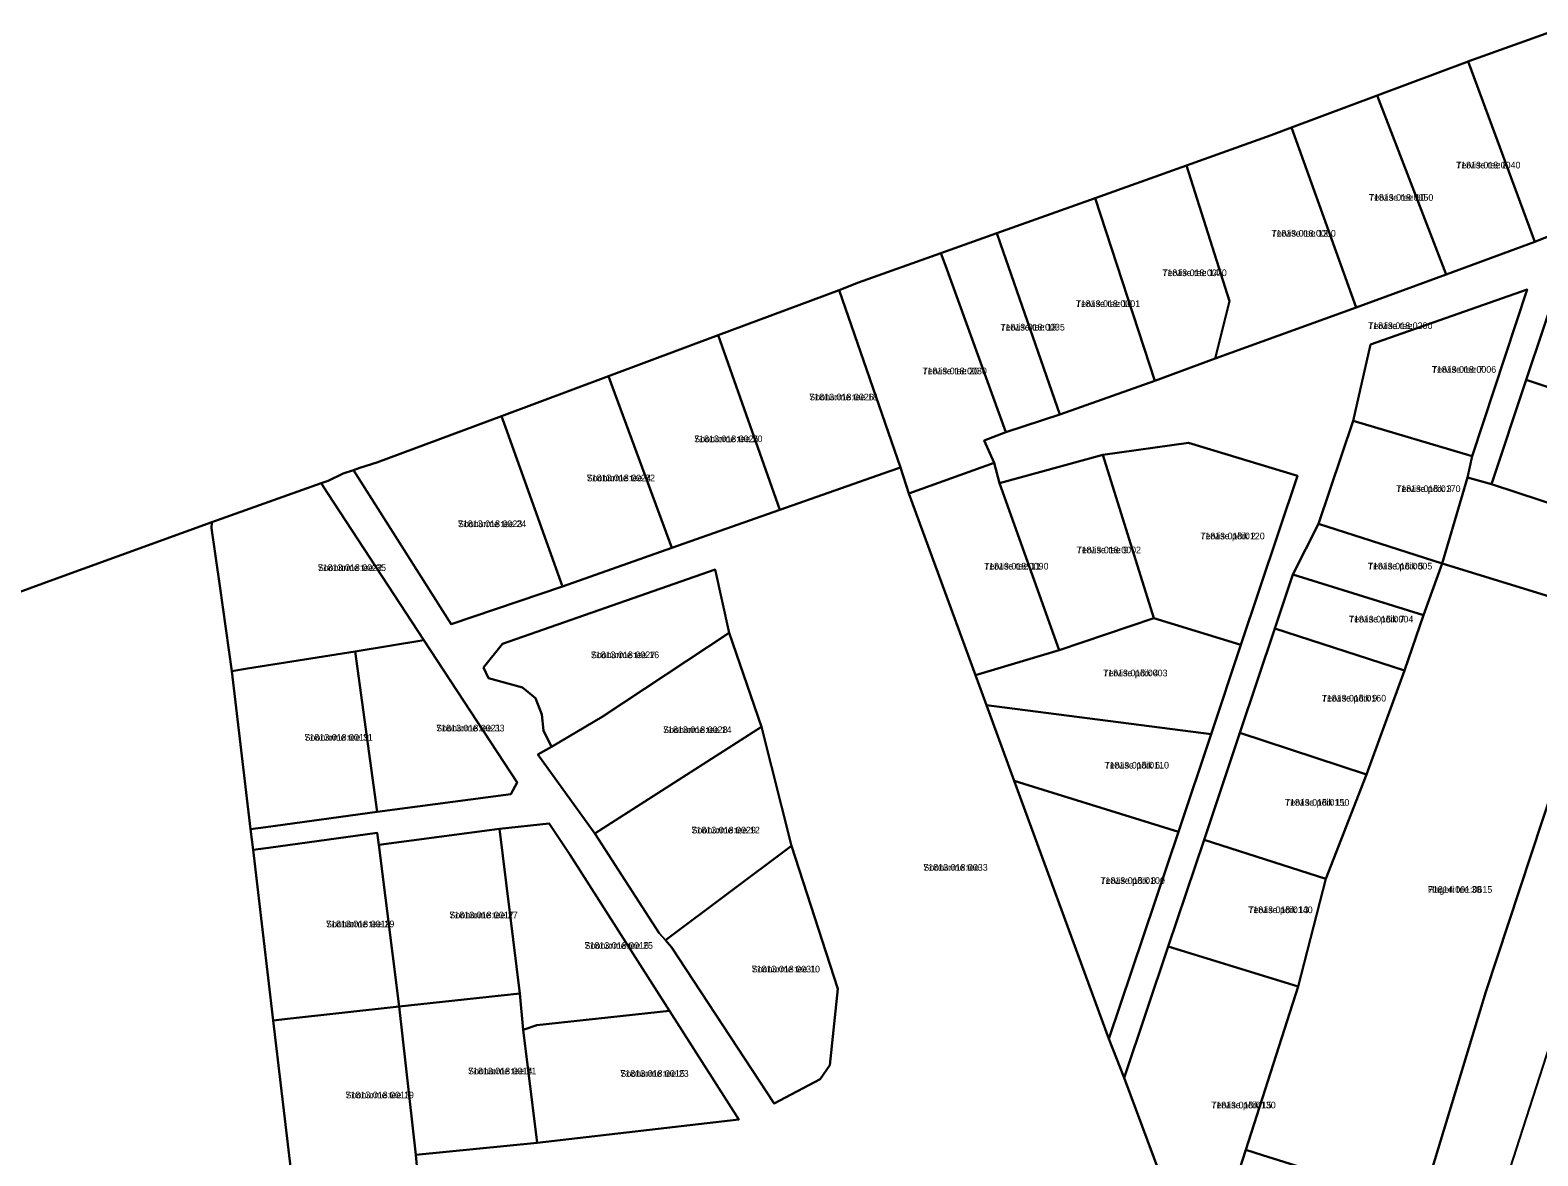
# Model space of a CAD drawing. Extents: x 529768 to 552006, y 6562269 to 6580975.
# Drawn here: x 537994.7 to 538334.3, y 6564944.1 to 6565197.7 of the extents above; entities that cross this region are included whole.
import ezdxf

# ---------------------------------------------------------------- set-up
doc = ezdxf.new("R2010")
doc.units = 0
for name, color, linetype in [('L_AADRESS', 7, 'Continuous'), ('PIIR', 7, 'Continuous'), ('TUNNUS', 7, 'Continuous')]:
    doc.layers.add(name, color=color, linetype=linetype)

msp = doc.modelspace()

# ---------------------------------------------------------------- linework, layer by layer
at = {"layer": 'PIIR'}
for points in [[(538338.26, 6565197.72), (538318.76, 6565190.73), (538318.58, 6565190.66), (538298.12, 6565183), (538278.82, 6565175.77), (538274.18, 6565174.03), (538255.15, 6565167.23), (538234.61, 6565159.87), (538212.42, 6565151.96), (538199.86, 6565147.46), (538181.3, 6565140.83), (538176.91, 6565139.17), (538149.69, 6565128.98), (538124.96, 6565119.74), (538100.9, 6565110.76), (538072.84, 6565100.28), (538068.99, 6565099.13), (538067.53, 6565098.62), (538065.21, 6565097.82), (538061.86, 6565096.19), (538060.26, 6565095.62), (538035.66, 6565086.9), (537999.88, 6565073.9), (537935.47, 6565050.3)], [(538339.3, 6565141.77), (538331.67, 6565118.94), (538323.82, 6565095.46), (538318.43, 6565096.95), (538319.45, 6565101.76), (538331.84, 6565139.3), (538296.57, 6565126.87), (538292.67, 6565109.72), (538284.89, 6565086.51), (538279.13, 6565075.05), (538275.06, 6565062.91), (538267.18, 6565039.43), (538259.11, 6565015.32), (538251.03, 6564991.25), (538241.13, 6564961.69), (538237.68, 6564970.44), (538253.34, 6565017.1), (538260.67, 6565039.07), (538267.42, 6565059.23), (538280.17, 6565097.32), (538255.63, 6565104.77), (538236.34, 6565102.01), (538213.04, 6565095.67), (538211.84, 6565100.22), (538209.58, 6565105.3), (538214.47, 6565107.11), (538226.65, 6565111.14), (538248.01, 6565118.69), (538261.59, 6565123.77), (538293.38, 6565135.23), (538313.64, 6565142.65), (538333.61, 6565150.05), (538353.15, 6565157.92)], [(538082.07, 6564939.35), (538081.58, 6564944.34), (538108.89, 6564947.05), (538154.33, 6564952.3), (538138.74, 6564976.77), (538116.27, 6565012.03), (538111.6, 6565019.01), (538100.44, 6565017.78), (538073.26, 6565014.19), (538072.89, 6565016.87), (538048.39, 6565013.51), (538044.93, 6565013.03), (538044.38, 6565017.68), (538047.81, 6565018.16), (538072.86, 6565021.59), (538102.97, 6565025.57), (538104.44, 6565028.24), (538083.43, 6565060.28), (538061.77, 6565093.31), (538060.26, 6565095.62), (538061.86, 6565096.19), (538065.21, 6565097.82), (538067.53, 6565098.62), (538069.12, 6565096.12), (538089.53, 6565063.89), (538114.61, 6565072.34), (538139.25, 6565081.05), (538163.58, 6565089.64), (538188.32, 6565098.37), (538190.71, 6565099.21), (538192.64, 6565093.3), (538207.61, 6565052.42), (538210.09, 6565045.62), (538216.32, 6565028.6), (538237.68, 6564970.44), (538241.13, 6564961.69), (538250.41, 6564936.65)], [(537935.47, 6565050.3), (537999.88, 6565073.9), (538035.66, 6565086.9), (538035.56, 6565085.5), (538037.44, 6565072.54), (538040.16, 6565053.32), (538044.38, 6565017.68), (538044.93, 6565013.03), (538049.48, 6564974.58), (538053.98, 6564936.59), (538054.5, 6564932.17), (538059.83, 6564887.16), (538062.92, 6564887.96), (538065.7, 6564865.25), (538069.71, 6564832.47), (538070.84, 6564823.25), (538069.52, 6564811.11), (538075.4, 6564804.88), (538059.69, 6564796.82), (538028.15, 6564780.63), (537982.75, 6564773.59)], [(538308.01, 6564933.07), (538322.57, 6564981.02), (538350.55, 6565065.93)], [(538336.86, 6564968.94), (538321.95, 6564922.64)]]:
    msp.add_lwpolyline(points, dxfattribs=at)
for points in [[(538318.58, 6565190.66), (538318.76, 6565190.73), (538338.26, 6565197.72), (538353.15, 6565157.92), (538333.61, 6565150.05)], [(538298.12, 6565183), (538318.58, 6565190.66), (538333.61, 6565150.05), (538313.64, 6565142.65)], [(538278.82, 6565175.77), (538298.12, 6565183), (538313.64, 6565142.65), (538293.38, 6565135.23)], [(538261.59, 6565123.77), (538264.81, 6565136.63), (538255.15, 6565167.23), (538274.18, 6565174.03), (538278.82, 6565175.77), (538293.38, 6565135.23)], [(538234.61, 6565159.87), (538255.15, 6565167.23), (538264.81, 6565136.63), (538261.59, 6565123.77), (538248.01, 6565118.69)], [(538248.01, 6565118.69), (538226.65, 6565111.14), (538213.27, 6565149.6), (538212.42, 6565151.96), (538234.61, 6565159.87)], [(538213.27, 6565149.6), (538226.65, 6565111.14), (538214.47, 6565107.11), (538200.84, 6565144.73), (538199.86, 6565147.46), (538212.42, 6565151.96)], [(538192.64, 6565093.3), (538190.71, 6565099.21), (538176.91, 6565139.17), (538181.3, 6565140.83), (538199.86, 6565147.46), (538200.84, 6565144.73), (538214.47, 6565107.11), (538209.58, 6565105.3), (538211.84, 6565100.22)], [(538339.3, 6565141.77), (538372.43, 6565133.83), (538364.67, 6565108), (538331.67, 6565118.94)], [(538149.69, 6565128.98), (538176.91, 6565139.17), (538190.71, 6565099.21), (538188.32, 6565098.37), (538163.58, 6565089.64), (538150.58, 6565126.48)], [(538319.45, 6565101.76), (538292.67, 6565109.72), (538296.57, 6565126.87), (538331.84, 6565139.3)], [(538124.96, 6565119.74), (538149.69, 6565128.98), (538150.58, 6565126.48), (538163.58, 6565089.64), (538139.25, 6565081.05), (538125.87, 6565117.29)], [(538100.9, 6565110.76), (538124.96, 6565119.74), (538125.87, 6565117.29), (538139.25, 6565081.05), (538114.61, 6565072.34), (538101.78, 6565108.3)], [(538356.96, 6565084.57), (538323.82, 6565095.46), (538331.67, 6565118.94), (538364.67, 6565108)], [(538067.53, 6565098.62), (538068.99, 6565099.13), (538072.84, 6565100.28), (538100.9, 6565110.76), (538101.78, 6565108.3), (538114.61, 6565072.34), (538089.53, 6565063.89), (538069.12, 6565096.12)], [(538292.67, 6565109.72), (538319.45, 6565101.76), (538318.43, 6565096.95), (538312.76, 6565077.58), (538284.89, 6565086.51)], [(538236.34, 6565102.01), (538255.63, 6565104.77), (538280.17, 6565097.32), (538267.42, 6565059.23), (538247.76, 6565065.21)], [(538211.84, 6565100.22), (538213.04, 6565095.67), (538226.49, 6565058.01), (538207.61, 6565052.42), (538192.64, 6565093.3)], [(538247.76, 6565065.21), (538226.49, 6565058.01), (538213.04, 6565095.67), (538236.34, 6565102.01)], [(538318.43, 6565096.95), (538323.82, 6565095.46), (538356.96, 6565084.57), (538350.55, 6565065.93), (538312.76, 6565077.58)], [(538035.66, 6565086.9), (538060.26, 6565095.62), (538061.77, 6565093.31), (538083.43, 6565060.28), (538067.92, 6565057.76), (538043.69, 6565053.89), (538040.16, 6565053.32), (538037.44, 6565072.54), (538035.56, 6565085.5)], [(538308.49, 6565065.91), (538279.13, 6565075.05), (538284.89, 6565086.51), (538312.76, 6565077.58)], [(538096.83, 6565054.16), (538101.11, 6565059.46), (538149.01, 6565076.21), (538152.13, 6565061.95), (538123.57, 6565043.01), (538112.13, 6565036.24), (538110.34, 6565039.92), (538109.96, 6565043.52), (538108.53, 6565047.24), (538105.65, 6565049.59), (538097.92, 6565051.69)], [(538096.83, 6565054.16), (538097.92, 6565051.69), (538105.65, 6565049.59), (538108.53, 6565047.24), (538109.96, 6565043.52), (538110.34, 6565039.92), (538112.13, 6565036.24), (538109.06, 6565034.51), (538121.87, 6565016.76), (538136.42, 6564994.24), (538137.79, 6564992.69), (538139.19, 6564991.14), (538162.28, 6564955.91), (538172.65, 6564961.39), (538174.84, 6564964.56), (538176.66, 6564981.73), (538166.17, 6565013.93), (538159.4, 6565040.78), (538152.13, 6565061.95), (538149.01, 6565076.21), (538101.11, 6565059.46)], [(538312.76, 6565077.58), (538350.55, 6565065.93), (538322.57, 6564981.02), (538308.01, 6564933.07), (538272.28, 6564944.25), (538268.48, 6564945.44), (538280.32, 6564982.23), (538286.55, 6565006.52), (538295.71, 6565030), (538304.22, 6565053.48), (538308.49, 6565065.91)], [(538304.22, 6565053.48), (538275.06, 6565062.91), (538279.13, 6565075.05), (538308.49, 6565065.91)], [(538260.67, 6565039.07), (538210.09, 6565045.62), (538207.61, 6565052.42), (538226.49, 6565058.01), (538247.76, 6565065.21), (538267.42, 6565059.23)], [(538275.06, 6565062.91), (538304.22, 6565053.48), (538295.71, 6565030), (538267.18, 6565039.43)], [(538067.92, 6565057.76), (538083.43, 6565060.28), (538104.44, 6565028.24), (538102.97, 6565025.57), (538072.86, 6565021.59)], [(538109.06, 6565034.51), (538112.13, 6565036.24), (538123.57, 6565043.01), (538152.13, 6565061.95), (538159.4, 6565040.78), (538121.87, 6565016.76)], [(538040.16, 6565053.32), (538043.69, 6565053.89), (538067.92, 6565057.76), (538072.86, 6565021.59), (538047.81, 6565018.16), (538044.38, 6565017.68)], [(538210.09, 6565045.62), (538260.67, 6565039.07), (538253.34, 6565017.1), (538216.32, 6565028.6)], [(538121.87, 6565016.76), (538159.4, 6565040.78), (538166.17, 6565013.93), (538137.79, 6564992.69), (538136.42, 6564994.24)], [(538267.18, 6565039.43), (538295.71, 6565030), (538286.55, 6565006.52), (538259.11, 6565015.32)], [(538253.34, 6565017.1), (538237.68, 6564970.44), (538216.32, 6565028.6)], [(538100.44, 6565017.78), (538111.6, 6565019.01), (538116.27, 6565012.03), (538138.74, 6564976.77), (538108.86, 6564973.52), (538105.8, 6564972.47), (538105.05, 6564980.66)], [(538044.93, 6565013.03), (538048.39, 6565013.51), (538072.89, 6565016.87), (538073.26, 6565014.19), (538077.81, 6564977.74), (538052.69, 6564974.94), (538049.48, 6564974.58)], [(538073.26, 6565014.19), (538100.44, 6565017.78), (538105.05, 6564980.66), (538077.81, 6564977.74)], [(538259.11, 6565015.32), (538286.55, 6565006.52), (538280.32, 6564982.23), (538251.03, 6564991.25)], [(538137.79, 6564992.69), (538166.17, 6565013.93), (538176.66, 6564981.73), (538174.84, 6564964.56), (538172.65, 6564961.39), (538162.28, 6564955.91), (538139.19, 6564991.14)], [(538241.13, 6564961.69), (538251.03, 6564991.25), (538280.32, 6564982.23), (538268.48, 6564945.44), (538259.79, 6564918.41), (538258.57, 6564914.59), (538255.85, 6564921.95), (538250.41, 6564936.65)], [(538049.48, 6564974.58), (538052.69, 6564974.94), (538077.81, 6564977.74), (538081.58, 6564944.34), (538082.07, 6564939.35), (538057.23, 6564936.91), (538053.98, 6564936.59)], [(538077.81, 6564977.74), (538105.05, 6564980.66), (538105.8, 6564972.47), (538108.89, 6564947.05), (538081.58, 6564944.34)], [(538105.8, 6564972.47), (538108.86, 6564973.52), (538138.74, 6564976.77), (538154.33, 6564952.3), (538108.89, 6564947.05)], [(538268.48, 6564945.44), (538272.28, 6564944.25), (538308.01, 6564933.07), (538302.72, 6564915.64), (538283.87, 6564853.73), (538282.62, 6564849.67), (538281.61, 6564852.4), (538271.72, 6564879.08), (538263.14, 6564902.26), (538258.57, 6564914.59), (538259.79, 6564918.41)]]:
    msp.add_lwpolyline(points, close=True, dxfattribs=at)

# ---------------------------------------------------------------- texts
at = {"layer": 'L_AADRESS'}
for s, p in [('Tervise tee 8', (538315.86, 6565166.56)), ('Tervise tee 10', (538296.23, 6565159.28)), ('Tervise tee 12', (538274.27, 6565151.2)), ('Tervise tee 14', (538249.71, 6565142.3)), ('Tervise tee 16', (538230.21, 6565135.35)), ('Tervise tee 18', (538213.25, 6565130.05)), ('Tervise tee', (538296.04, 6565130.38)), ('Tervise tee 20', (538195.69, 6565120.18)), ('Tervise tee 7', (538310.39, 6565120.53)), ('Soonurme tee 18', (538170.2, 6565114.32)), ('Soonurme tee 20', (538144.27, 6565104.89)), ('Soonurme tee 22', (538120.07, 6565096.09)), ('Tervise põik 3', (538302.37, 6565093.65)), ('Soonurme tee 24', (538091.07, 6565085.75)), ('Tervise põik 2', (538258.26, 6565083)), ('Tervise tee 9', (538230.4, 6565079.86)), ('Soonurme tee 35', (538059.5, 6565075.88)), ('Tervise tee 11', (538209.57, 6565076.2)), ('Tervise põik 5', (538295.99, 6565076.21)), ('Tervise põik 7', (538291.72, 6565064.27)), ('Soonurme tee 16', (538121, 6565056.23)), ('Tervise põik 4', (538236.38, 6565052.14)), ('Tervise põik 9', (538285.61, 6565046.46)), ('Soonurme tee 31', (538056.51, 6565037.64)), ('Soonurme tee 33', (538086.18, 6565039.72)), ('Soonurme tee 14', (538137.28, 6565039.36)), ('Tervise põik 6', (538236.7, 6565031.36)), ('Tervise põik 11', (538277.32, 6565022.98)), ('Soonurme tee 12', (538143.67, 6565016.74)), ('Soonurme tee', (538195.88, 6565008.34)), ('Tervise põik 8', (538235.78, 6565005.38)), ('Hageri tee 38', (538309.51, 6565003.37)), ('Soonurme tee 27', (538089.15, 6564997.62)), ('Tervise põik 13', (538269.06, 6564998.78)), ('Soonurme tee 29', (538061.37, 6564995.6)), ('Soonurme tee 25', (538119.59, 6564990.75)), ('Soonurme tee 10', (538157.22, 6564985.43)), ('Soonurme tee 21', (538093.35, 6564962.46)), ('Soonurme tee 23', (538127.65, 6564961.91)), ('Soonurme tee 19', (538065.77, 6564957.07)), ('Tervise põik 15', (538260.73, 6564954.79))]:
    msp.add_text(s, height=1.5, dxfattribs=at).set_placement(p)
at = {"layer": 'TUNNUS'}
for s, p in [('71813:018:0040', (538315.86, 6565166.56)), ('71813:018:0050', (538296.23, 6565159.28)), ('71813:018:0060', (538274.27, 6565151.2)), ('71813:018:0070', (538249.71, 6565142.3)), ('71813:018:0001', (538230.21, 6565135.35)), ('71813:018:0035', (538213.25, 6565130.05)), ('71813:018:0200', (538296.04, 6565130.38)), ('71813:018:0080', (538195.69, 6565120.18)), ('71813:018:0006', (538310.39, 6565120.53)), ('71813:018:0026', (538170.2, 6565114.32)), ('71813:018:0025', (538144.27, 6565104.89)), ('71813:018:0024', (538120.07, 6565096.09)), ('71813:018:0170', (538302.37, 6565093.65)), ('71813:018:0023', (538091.07, 6565085.75)), ('71813:018:0120', (538258.26, 6565083)), ('71813:018:0002', (538230.4, 6565079.86)), ('71813:018:0022', (538059.5, 6565075.88)), ('71813:018:0090', (538209.57, 6565076.2)), ('71813:018:0005', (538295.99, 6565076.21)), ('71813:018:0004', (538291.72, 6565064.27)), ('71813:018:0027', (538121, 6565056.23)), ('71813:018:0003', (538236.38, 6565052.14)), ('71813:018:0160', (538285.61, 6565046.46)), ('71813:018:0019', (538056.51, 6565037.64)), ('71813:018:0021', (538086.18, 6565039.72)), ('71813:018:0028', (538137.28, 6565039.36)), ('71813:018:0110', (538236.7, 6565031.36)), ('71813:018:0150', (538277.32, 6565022.98)), ('71813:018:0029', (538143.67, 6565016.74)), ('71813:018:0033', (538195.88, 6565008.34)), ('71813:018:0100', (538235.78, 6565005.38)), ('71814:001:0615', (538309.51, 6565003.37)), ('71813:018:0017', (538089.15, 6564997.62)), ('71813:018:0140', (538269.06, 6564998.78)), ('71813:018:0018', (538061.37, 6564995.6)), ('71813:018:0016', (538119.59, 6564990.75)), ('71813:018:0031', (538157.22, 6564985.43)), ('71813:018:0014', (538093.35, 6564962.46)), ('71813:018:0015', (538127.65, 6564961.91)), ('71813:018:0013', (538065.77, 6564957.07)), ('71813:018:0130', (538260.73, 6564954.79))]:
    msp.add_text(s, height=1.5, dxfattribs=at).set_placement(p)

doc.saveas('drawing.dxf')
